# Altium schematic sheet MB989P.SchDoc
size A4; Revision: B.1
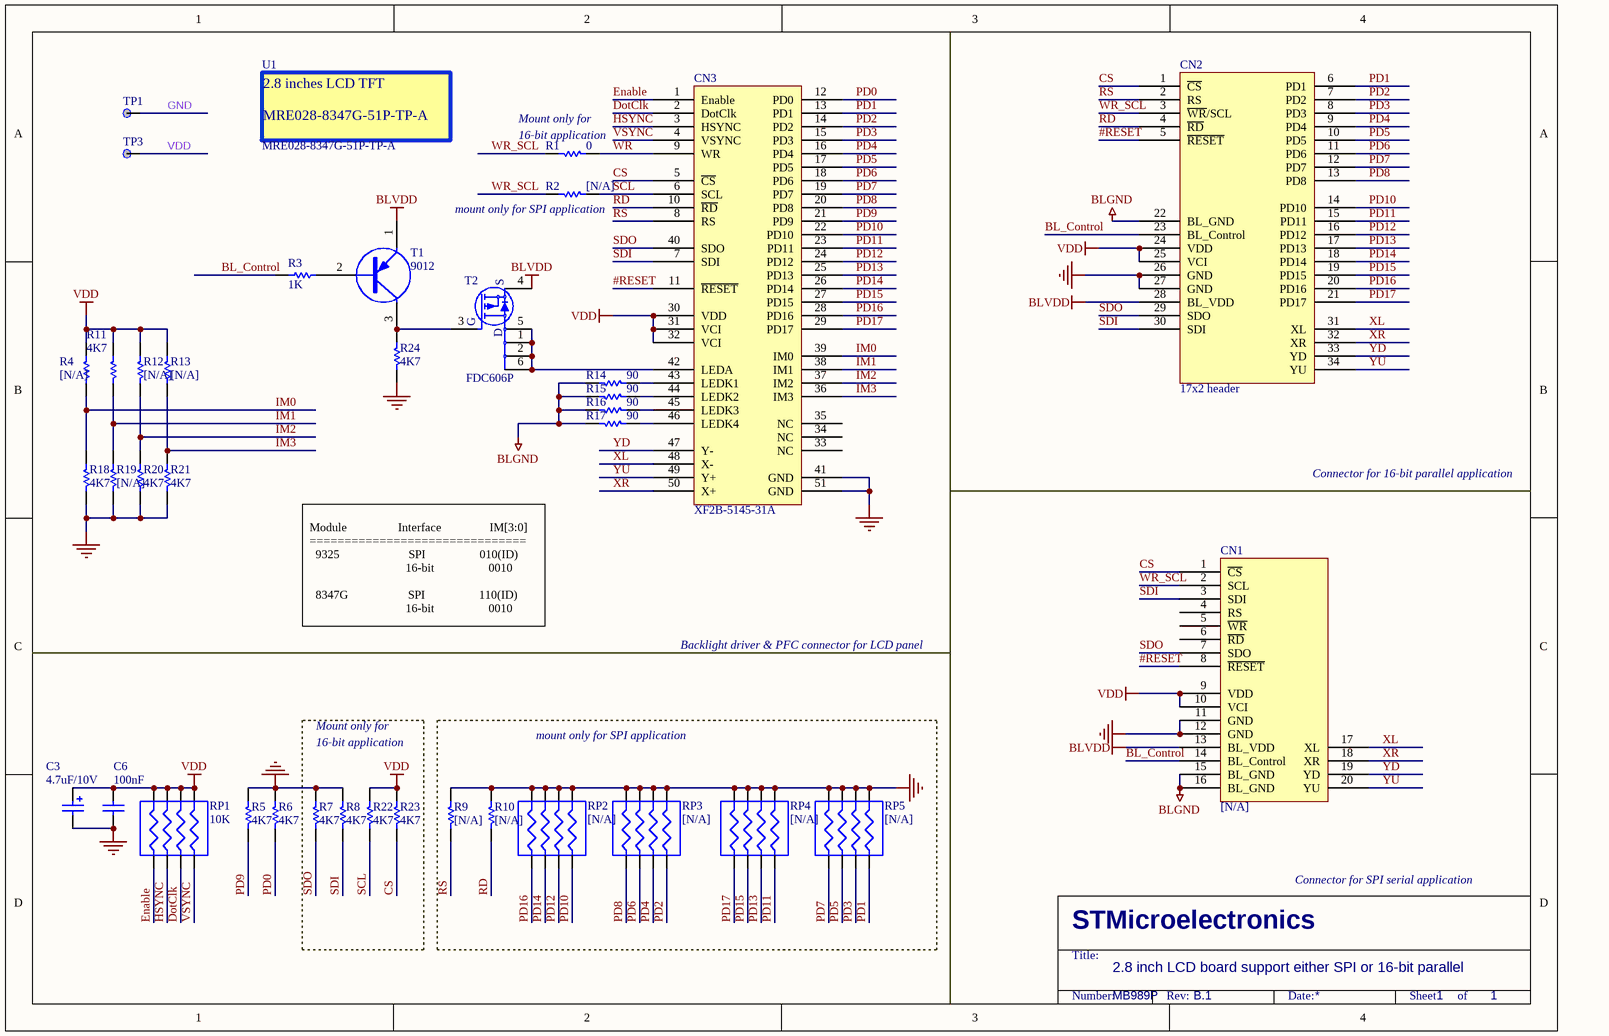
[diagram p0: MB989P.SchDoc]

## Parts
C3  4.7uF/10V  [TAN-A]
C6  100nF  [0603C]
CN1  [N/A]  [AM240320A]
CN2  17x2 header  [2*17P]
CN3  XF2B-5145-31A  [XF2B-5145]
R1  0  [0603R]
R2  [N/A]  [0603R]
R3  1K  [0603R]
R4  [N/A]  [0603R]
R5  4K7  [0603R]
R6  4K7  [0603R]
R7  4K7  [0603R]
R8  4K7  [0603R]
R9  [N/A]  [0603R]
R10  [N/A]  [0603R]
R11  4K7  [0603R]
R12  [N/A]  [0603R]
R13  [N/A]  [0603R]
R14  90  [0603R]
R15  90  [0603R]
R16  90  [0603R]
R17  90  [0603R]
R18  4K7  [0603R]
R19  [N/A]  [0603R]
R20  4K7  [0603R]
R21  4K7  [0603R]
R22  4K7  [0603R]
R23  4K7  [0603R]
R24  4K7  [0603R]
RP1  10K  [RES-4B]
RP2  [N/A]  [RES-4B]
RP3  [N/A]  [RES-4B]
RP4  [N/A]  [RES-4B]
RP5  [N/A]  [RES-4B]
T1  9012  [SOT-23]
T2  FDC606P  [SOT23-6L]
TP1  (no value)  [TP]
TP3  (no value)  [TP]
U1  MRE028-8347G-51P-TP-A

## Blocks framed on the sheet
mount only for SPI application: R9 R10 RP2-RP5

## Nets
BLGND: CN1.15(BL_GND) CN1.16(BL_GND) CN2.22(BL_GND) R14.2 R15.2 R16.2 R17.2
BLVDD: CN1.13(BL_VDD) CN2.28(BL_VDD) T1.1(E) T2.4(S)
GND: C3.2 C6.1 CN1.11(GND) CN1.12(GND) CN2.26(GND) CN2.27(GND) CN3.41(GND) CN3.51(GND) R5.1 R6.1 R7.1 R8.1 R9.1 R10.1 R18.2 R19.2 R20.2 R21.2 R24.2 RP2.2(R1) RP2.4(R3) RP2.6(R2) RP2.8(R0) RP3.2(R1) RP3.4(R3) RP3.6(R2) RP3.8(R0) RP4.2(R1) RP4.4(R3) RP4.6(R2) RP4.8(R0) RP5.2(R1) RP5.4(R3) RP5.6(R2) RP5.8(R0) TP1.1
VDD: C3.1 C6.2 CN1.9(VDD) CN1.10(VCI) CN2.24(VDD) CN2.25(VCI) CN3.30(VDD) CN3.31(VCI) CN3.32(VCI) R4.1 R11.1 R12.1 R13.1 R22.1 R23.1 RP1.2(R1) RP1.4(R3) RP1.6(R2) RP1.8(R0) TP3.1
#RESET: CN1.8(~{RESET}) CN2.5(~{RESET}) CN3.11(~{RESET})
BL_Control: CN1.14(BL_Control) CN2.23(BL_Control) R3.2
CS: CN1.1(~{CS}) CN2.1(~{CS}) CN3.5(~{CS}) R23.2
DotClk: CN3.2(DotClk) RP1.5(R3)
Enable: CN3.1(Enable) RP1.1(R0)
HSYNC: CN3.3(HSYNC) RP1.3(R2)
IM0: CN3.39(IM0) R4.2 R18.1
IM1: CN3.38(IM1) R11.2 R19.1
IM2: CN3.37(IM2) R12.2 R20.1
IM3: CN3.36(IM3) R13.2 R21.1
PD0: CN3.12(PD0) R6.2
PD1: CN2.6(PD1) CN3.13(PD1) RP5.7(R1)
PD2: CN2.7(PD2) CN3.14(PD2) RP3.7(R1)
PD3: CN2.8(PD3) CN3.15(PD3) RP5.5(R3)
PD4: CN2.9(PD4) CN3.16(PD4) RP3.5(R3)
PD5: CN2.10(PD5) CN3.17(PD5) RP5.3(R2)
PD6: CN2.11(PD6) CN3.18(PD6) RP3.3(R2)
PD7: CN2.12(PD7) CN3.19(PD7) RP5.1(R0)
PD8: CN2.13(PD8) CN3.20(PD8) RP3.1(R0)
PD9: CN3.21(PD9) R5.2
PD10: CN2.14(PD10) CN3.22(PD10) RP2.7(R1)
PD11: CN2.15(PD11) CN3.23(PD11) RP4.7(R1)
PD12: CN2.16(PD12) CN3.24(PD12) RP2.5(R3)
PD13: CN2.17(PD13) CN3.25(PD13) RP4.5(R3)
PD14: CN2.18(PD14) CN3.26(PD14) RP2.3(R2)
PD15: CN2.19(PD15) CN3.27(PD15) RP4.3(R2)
PD16: CN2.20(PD16) CN3.28(PD16) RP2.1(R0)
PD17: CN2.21(PD17) CN3.29(PD17) RP4.1(R0)
RD: CN2.4(~{RD}) CN3.10(~{RD}) R10.2
RS: CN2.2(RS) CN3.8(RS) R9.2
SCL: CN3.6(SCL) R2.1 R22.2
SDI: CN1.3(SDI) CN2.30(SDI) CN3.7(SDI) R8.2
SDO: CN1.7(SDO) CN2.29(SDO) CN3.40(SDO) R7.2
VSYNC: CN3.4(VSYNC) RP1.7(R1)
WR: CN3.9(WR) R1.1
WR_SCL: CN1.2(SCL) CN2.3(~{WR}/SCL) R1.2 R2.2
XL: CN1.17(XL) CN2.31(XL) CN3.48(X-)
XR: CN1.18(XR) CN2.32(XR) CN3.50(X+)
YD: CN1.19(YD) CN2.33(YD) CN3.47(Y-)
YU: CN1.20(YU) CN2.34(YU) CN3.49(Y+)
NetCN3_42: CN3.42(LEDA) T2.1(D) T2.2(D) T2.5(D) T2.6(D)
NetCN3_43: CN3.43(LEDK1) R14.1
NetCN3_44: CN3.44(LEDK2) R15.1
NetCN3_45: CN3.45(LEDK3) R16.1
NetCN3_46: CN3.46(LEDK4) R17.1
NetR3_1: R3.1 T1.2(B)
NetR24_1: R24.1 T1.3(C) T2.3(G)

Not connected (* = marked no-connect by the designer): CN1 4(RS) 5(~{WR}) 6(~{RD}); CN3 33(NC) 34(NC) 35(NC)

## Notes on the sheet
- (near R1) Mount only for
- (near R1) 16-bit application
- (near R2) mount only for SPI application
- Connector for 16-bit parallel application
- Module                 Interface                IM[3:0]
  ===============================
  9325                       SPI                  010(ID)
  16-bit                  0010
  8347G                    SPI                  110(ID)
  16-bit                  0010
- Backlight driver & PFC connector for LCD panel
- Mount only for
- 16-bit application
- Connector for SPI serial application
- 2.8 inch LCD board support either SPI or 16-bit parallel
- MB989P
- 1

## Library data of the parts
C3 = Cap Pol1: Polarized Capacitor (Radial); Value: 100pF
C6 = CAP: Capacitor; Value: 100pF
CN1 = ColorLCD_module_SPI
CN2 = ColorLCD_module_16bits
CN3 = MR028-9325-51P-TP-A: OMRON FCP connector
R1 R2 R4-R24 = Res1: Resistor; Value: 1K
R3 = Res1: Resistor
RP1-RP5 = RES4B
T1 = PNP
T2 = STT5PF20V
TP1 TP3 = TP
U1 = MRE028-8347G-51P-TP-A: LCD TFT 2.8'' screen - manufacturer OMRON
